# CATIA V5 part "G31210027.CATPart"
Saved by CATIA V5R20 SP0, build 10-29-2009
Part number: G31210027
Revision: 10
Definition: design
Nomenclature: G31210027
Source: made
Description: NOT SPECIFIED
Bounding box of the stored display mesh (mm): x -5 to 27, y -8 to 8, z -8 to 8
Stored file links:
  C:\Users\Raffaele\Desktop\3D X SITO CF\BOLEX\23-BUSH REF 312\G31210027.CATPart

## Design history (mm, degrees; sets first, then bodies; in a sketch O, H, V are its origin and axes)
Body1 "MANIFOLD_SOLID_BREP #7395" (main body)
  Solid1: solid without history
Body2 "MANIFOLD_SOLID_BREP #7538"
  Solid2: solid without history
Body3 "MANIFOLD_SOLID_BREP #7681"
  Solid3: solid without history
Body4 "MANIFOLD_SOLID_BREP #7824"
  Solid4: solid without history
Body5 "MANIFOLD_SOLID_BREP #7967"
  Solid5: solid without history
Body6 "MANIFOLD_SOLID_BREP #8110"
  Solid6: solid without history
Body7 "MANIFOLD_SOLID_BREP #8253"
  Solid7: solid without history
Body8 "MANIFOLD_SOLID_BREP #8398"
  Solid8: solid without history
Body9 "MANIFOLD_SOLID_BREP #8543"
  Solid9: solid without history
Body10 "MANIFOLD_SOLID_BREP #8688"
  Solid10: solid without history
Body11 "MANIFOLD_SOLID_BREP #8833"
  Solid11: solid without history
Body12 "MANIFOLD_SOLID_BREP #8976"
  Solid12: solid without history
Body13 "MANIFOLD_SOLID_BREP #9119"
  Solid13: solid without history
Body14 "MANIFOLD_SOLID_BREP #9264"
  Solid14: solid without history
Body15 "MANIFOLD_SOLID_BREP #9409"
  Solid15: solid without history
Body16 "MANIFOLD_SOLID_BREP #9554"
  Solid16: solid without history
Body17 "MANIFOLD_SOLID_BREP #9699"
  Solid17: solid without history
Body18 "MANIFOLD_SOLID_BREP #9844"
  Solid18: solid without history
Body19 "MANIFOLD_SOLID_BREP #9989"
  Solid19: solid without history
Body20 "MANIFOLD_SOLID_BREP #10134"
  Solid20: solid without history
Body21 "MANIFOLD_SOLID_BREP #10277"
  Solid21: solid without history
Body22 "MANIFOLD_SOLID_BREP #10420"
  Solid22: solid without history
Body23 "MANIFOLD_SOLID_BREP #10565"
  Solid23: solid without history
Body24 "MANIFOLD_SOLID_BREP #10708"
  Solid24: solid without history
Body25 "MANIFOLD_SOLID_BREP #10853"
  Solid25: solid without history
Body26 "MANIFOLD_SOLID_BREP #10998"
  Solid26: solid without history
Body27 "MANIFOLD_SOLID_BREP #11141"
  Solid27: solid without history
Body28 "MANIFOLD_SOLID_BREP #11284"
  Solid28: solid without history
Body29 "MANIFOLD_SOLID_BREP #11429"
  Solid29: solid without history
Body30 "MANIFOLD_SOLID_BREP #11574"
  Solid30: solid without history
Body31 "MANIFOLD_SOLID_BREP #11717"
  Solid31: solid without history
Body32 "MANIFOLD_SOLID_BREP #11862"
  Solid32: solid without history
Body33 "MANIFOLD_SOLID_BREP #12007"
  Solid33: solid without history
Body34 "MANIFOLD_SOLID_BREP #12150"
  Solid34: solid without history
Body35 "MANIFOLD_SOLID_BREP #12293"
  Solid35: solid without history
Body36 "MANIFOLD_SOLID_BREP #12436"
  Solid36: solid without history
Body37 "MANIFOLD_SOLID_BREP #12579"
  Solid37: solid without history
Body38 "MANIFOLD_SOLID_BREP #12724"
  Solid38: solid without history
Body39 "MANIFOLD_SOLID_BREP #12867"
  Solid39: solid without history
Body40 "MANIFOLD_SOLID_BREP #13012"
  Solid40: solid without history
Body41 "MANIFOLD_SOLID_BREP #13157"
  Solid41: solid without history
Body42 "MANIFOLD_SOLID_BREP #13300"
  Solid42: solid without history
Body43 "MANIFOLD_SOLID_BREP #13443"
  Solid43: solid without history
Body44 "MANIFOLD_SOLID_BREP #13588"
  Solid44: solid without history
Body45 "MANIFOLD_SOLID_BREP #13733"
  Solid45: solid without history
Body46 "MANIFOLD_SOLID_BREP #13876"
  Solid46: solid without history
Body47 "MANIFOLD_SOLID_BREP #14021"
  Solid47: solid without history
Body48 "MANIFOLD_SOLID_BREP #14166"
  Solid48: solid without history
Body49 "MANIFOLD_SOLID_BREP #14309"
  Solid49: solid without history
Body50 "MANIFOLD_SOLID_BREP #14452"
  Solid50: solid without history
Body51 "MANIFOLD_SOLID_BREP #14597"
  Solid51: solid without history
Body52 "MANIFOLD_SOLID_BREP #14740"
  Solid52: solid without history
Body53 "MANIFOLD_SOLID_BREP #14885"
  Solid53: solid without history
Body54 "MANIFOLD_SOLID_BREP #15030"
  Solid54: solid without history
Body55 "MANIFOLD_SOLID_BREP #15173"
  Solid55: solid without history
Body56 "MANIFOLD_SOLID_BREP #15316"
  Solid56: solid without history
Body57 "MANIFOLD_SOLID_BREP #15459"
  Solid57: solid without history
